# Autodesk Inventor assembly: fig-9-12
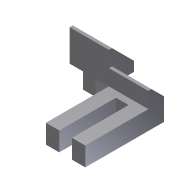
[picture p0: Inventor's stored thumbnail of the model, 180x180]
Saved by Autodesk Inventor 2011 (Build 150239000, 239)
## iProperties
Shininess: 64.0
Length Units: 11269
Angle Units: 11279
Time Units: 11290
Mass Units: 11283
Length Display Precision: 3
Angle Display Precision: 2
Created: 2002-01
Part Number: fig-9-12
Document SubType Name: Assembly
Designer: ***
Density: 0.0
Volumn: 0.0
Area: 0.0
PropertySet Name: Model Information
Control State: 0
Master: False
Checked Out: False
Author: ***
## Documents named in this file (3)
- C:\Users\CADSoft\Desktop\part files\c09-inv-2011-prt\fig-9-12.iam
- C:\Users\CADSoft\Desktop\inventor\c09-inv-2010-prt\c09\Part3.ipt
- C:\Users\CADSoft\Desktop\inventor\c09-inv-2010-prt\c09\Part4.ipt
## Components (2 placed, 2 different names)
1. Part3:1 — Flush:1
2. Part4:1 — Flush:1
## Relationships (1: Flush 1)
- Flush:1: Part3:1 ↔ Part4:1
